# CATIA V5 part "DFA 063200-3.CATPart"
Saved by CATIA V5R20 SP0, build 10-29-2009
Part number: DFA 063200-3
Revision: ANY
Definition: UNKNOWN
Nomenclature: DFA 063200-3
Source: Unknown
Bounding box of the stored display mesh (mm): x -2.109 to 2.109, y -2.45 to 2.45, z -2 to 2
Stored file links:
  C:\Users\Utente\Desktop\IO LAVORO\3D X SITO CF\CUMSA\3D files FA\FA 063205-21\DFA 063200-3.CATPart

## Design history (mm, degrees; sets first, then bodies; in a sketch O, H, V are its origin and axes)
Body1 "Chaflán4" (main body)
  Solid1: solid without history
